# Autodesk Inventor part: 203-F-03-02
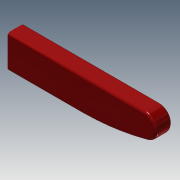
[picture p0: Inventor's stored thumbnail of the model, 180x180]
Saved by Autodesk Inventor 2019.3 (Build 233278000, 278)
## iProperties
Created: 2011-05
Part Number: 203-F-03-02
Material: Ogólny
Document SubType Name: Modeling
Designer: CADENGINEERING4
Density: 1 g/cm^3
Appearance: Czerwona
Author: CADENGINEERING4
Revision Number: ÈÎºÎ
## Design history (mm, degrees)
feature "³é¿Ç2"
node "Bryła1"
